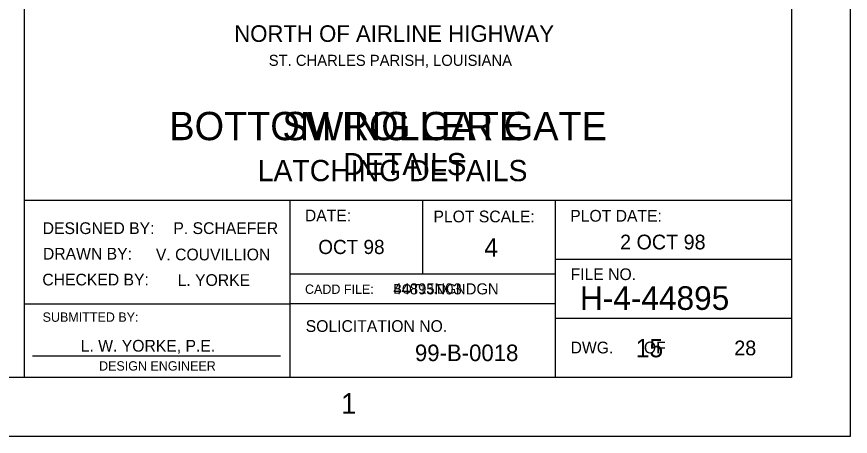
# Model space of a CAD drawing. Extents: x 0 to 13.3, y 0 to 9.3.
# Drawn here: x 10.977 to 13.333, y 0 to 1.187 of the extents above; entities that cross this region are included whole.
import ezdxf

# ---------------------------------------------------------------- set-up
doc = ezdxf.new("R2010")
doc.units = 0
doc.layers.add('Level 1', color=7, linetype='Continuous')
doc.layers.add('Level 2', color=7, linetype='Continuous')

msp = doc.modelspace()

# ---------------------------------------------------------------- linework, layer by layer
at = {"layer": 'Level 1'}
for p, q in [((11, 0.1667), (11, 1.75)), ((13.1667, 0.6667), (11, 0.6667)), ((11.75, 0.1667), (11.75, 0.6667)), ((12.125, 0.4583), (12.125, 0.6667)), ((12.5, 0.1667), (12.5, 0.6667)), ((13.1667, 0.5), (12.5, 0.5)), ((12.5, 0.4583), (11.75, 0.4583)), ((11, 0.375), (11.75, 0.375)), ((12.5, 0.375), (11.75, 0.375)), ((13.1667, 0.3333), (12.5, 0.3333)), ((13.1667, 0.3333), (12.5, 0.3333)), ((11.0224, 0.2278), (11.7234, 0.2278))]:
    msp.add_line(p, q, dxfattribs=at)
for points in [[(0, 9.3333), (13.3333, 9.3333), (13.3333, 0), (0, 0)], [(0.5, 9.1667), (13.1667, 9.1667), (13.1667, 0.1667), (0.5, 0.1667)]]:
    msp.add_lwpolyline(points, close=True, dxfattribs=at)

# ---------------------------------------------------------------- texts
for s, height, p in [('DATE:', 0.03321, (11.792, 0.6079)), ('PLOT SCALE:', 0.033208, (12.1552, 0.605)), ('PLOT DATE:', 0.03321, (12.5418, 0.6069)), ('DESIGNED BY:', 0.033208, (11.051, 0.5719)), ('DRAWN BY:', 0.03321, (11.0517, 0.4997)), ('FILE NO.', 0.03321, (12.5428, 0.4417)), ('CHECKED BY:', 0.033208, (11.05, 0.4266)), ('CADD FILE:', 0.02642, (11.7923, 0.4028)), ('SUBMITTED BY:', 0.026417, (11.0508, 0.3239)), ('SOLICITATION NO.', 0.033208, (11.7943, 0.2952)), ('DWG.       OF', 0.033208, (12.5428, 0.2345)), ('DESIGN ENGINEER', 0.026417, (11.2103, 0.1859)), ('1', 0.0584, (11.8942, 0.0637))]:
    msp.add_text(s, height=height, dxfattribs=at).set_placement(p)
at = {"layer": 'Level 2'}
for s, height, p in [('NORTH OF AIRLINE HIGHWAY', 0.046792, (11.5922, 1.1153)), ('ST. CHARLES PARISH, LOUISIANA', 0.03125, (11.6898, 1.0474)), ('BOTTOM ROLLER GATE', 0.08, (11.409, 0.8373)), ('SWING GATE', 0.08, (11.7283, 0.8373)), ('DETAILS', 0.0625, (11.9001, 0.7385)), ('LATCHING DETAILS', 0.059999, (11.6586, 0.7214)), ('P. SCHAEFER', 0.033208, (11.4203, 0.572)), ('2 OCT 98', 0.04167, (12.6827, 0.5285)), ('OCT 98', 0.04, (11.8298, 0.5154)), ('4', 0.0521, (12.2989, 0.5078)), ('V. COUVILLION', 0.033208, (11.3709, 0.4975)), ('L. YORKE', 0.03321, (11.4323, 0.4252)), ('44895N03.DGN', 0.03125, (12.0421, 0.4013)), ('BOT13.DGN', 0.02679, (12.0421, 0.4035)), ('H-4-44895', 0.06679, (12.5692, 0.3575)), ('L. W. YORKE, P.E.', 0.033208, (11.1585, 0.2394)), ('99-B-0018', 0.04679, (12.103, 0.2127)), ('15', 0.05208, (12.7269, 0.2235)), ('28', 0.04167, (13.0054, 0.2291))]:
    msp.add_text(s, height=height, dxfattribs=at).set_placement(p)

doc.saveas('drawing.dxf')
